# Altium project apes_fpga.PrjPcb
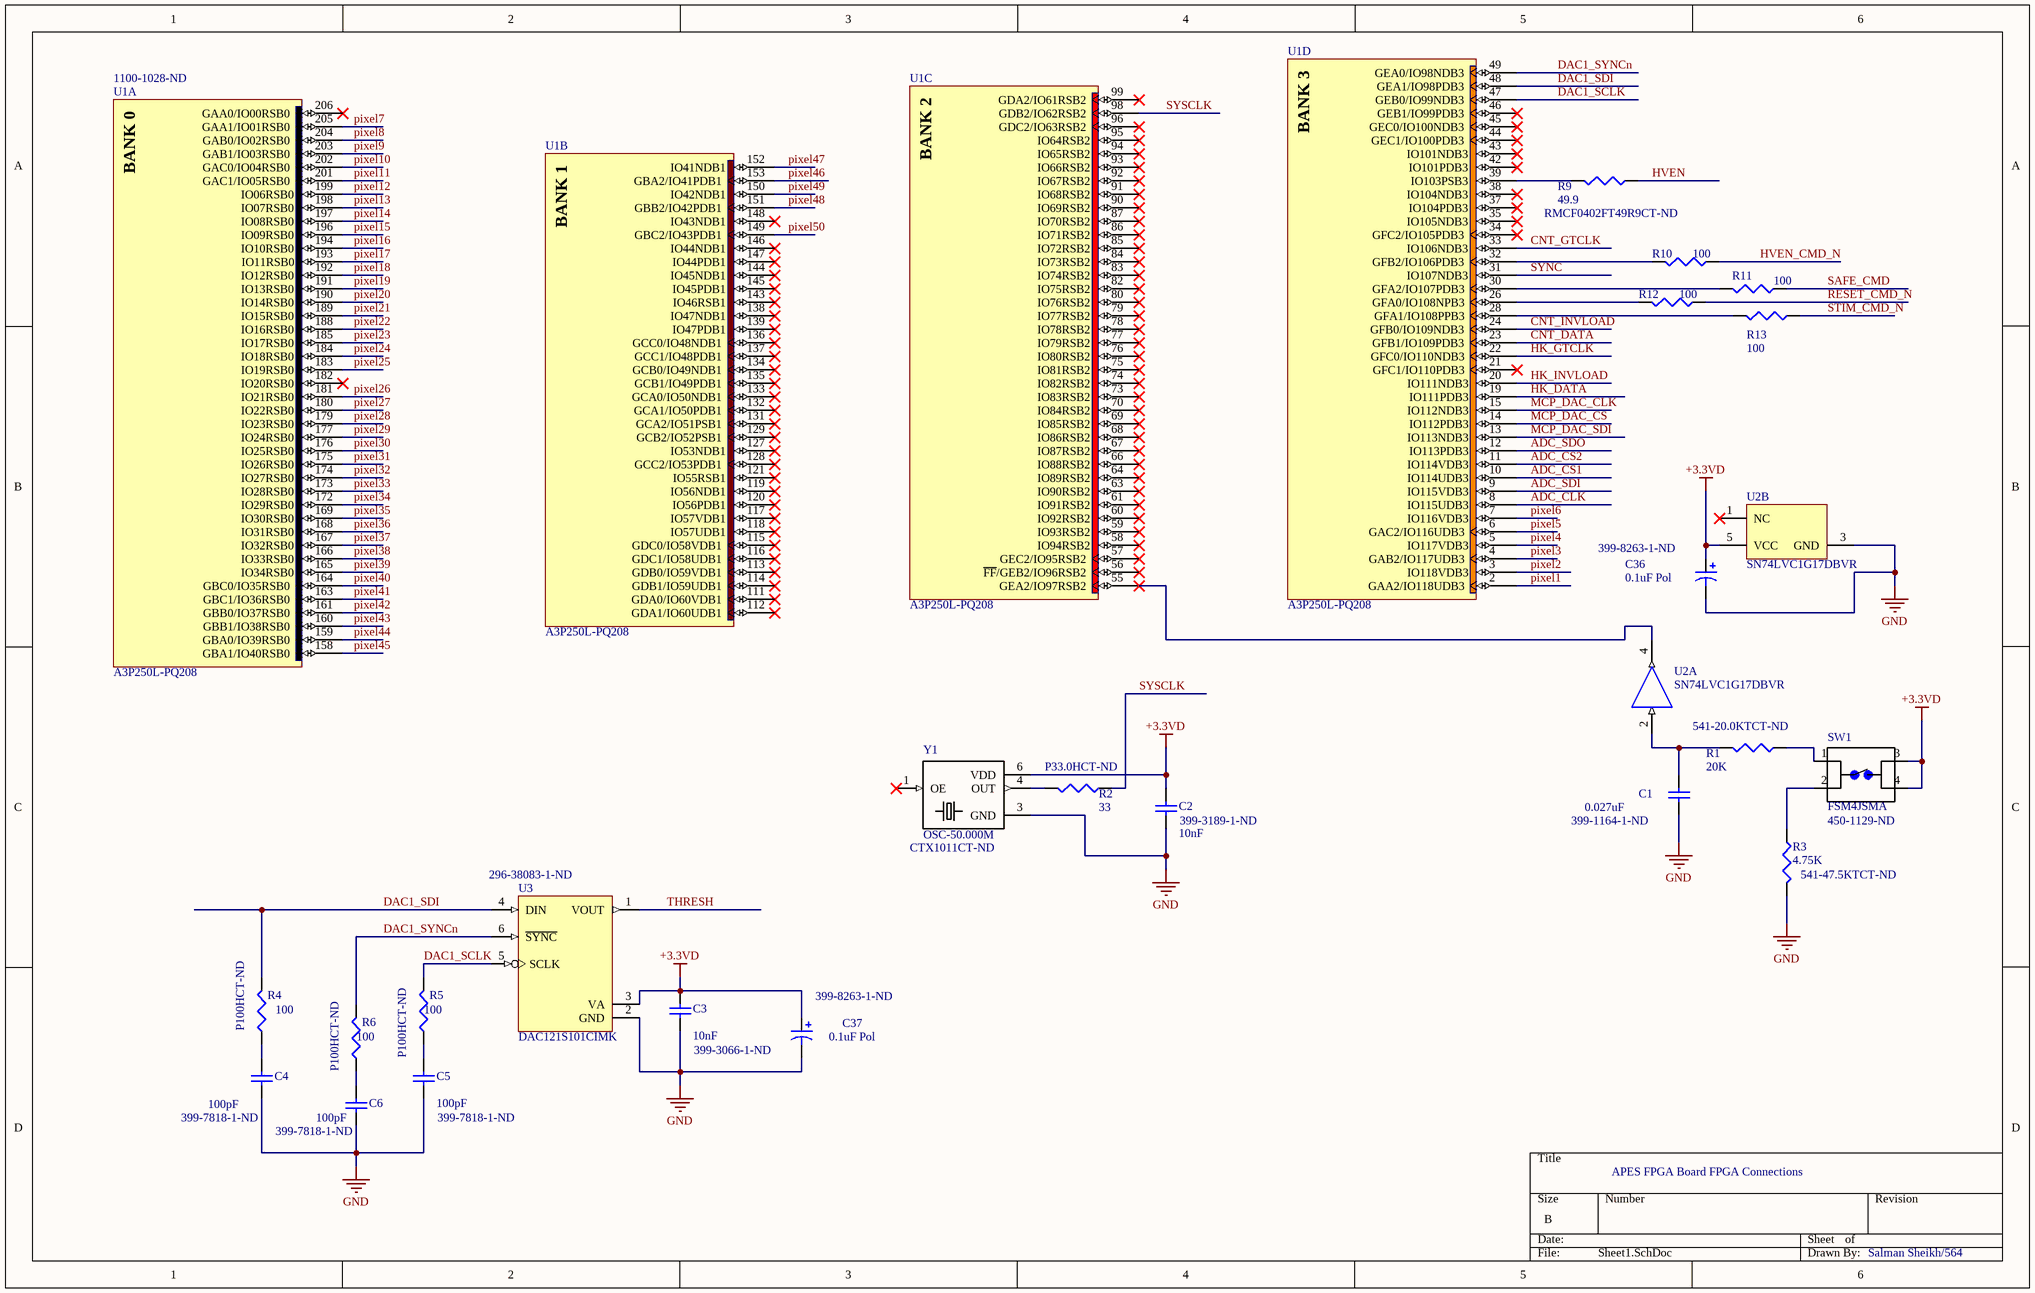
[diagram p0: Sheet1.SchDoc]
3 sheets, 66 parts. Net scope: global (net labels, ports and power ports of the same name join across sheets).
Board file: FPGA.PcbDoc
Sheets:
  Sheet1.SchDoc
  Sheet3.SchDoc
  Sheet2.SchDoc

## Sheet Sheet1.SchDoc
size B

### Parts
C1  value 0.027uF  Supplier Part Number 1: 399-1164-1-ND  [C0805]  (hidden comment: Cap Semi)
C2  value 10nF  Supplier Part Number 1: 399-3189-1-ND  [1608[0603]]  (hidden comment: Cap Semi)
C3  value 10nF  Supplier Part Number 1: 399-3066-1-ND  [0402]  (hidden comment: Cap Semi)
C4  value 100pF  Supplier Part Number 1: 399-7818-1-ND  [1608[0603]]  (hidden comment: Cap Semi)
C5  value 100pF  Supplier Part Number 1: 399-7818-1-ND  [1608[0603]]  (hidden comment: Cap Semi)
C6  value 100pF  Supplier Part Number 1: 399-7818-1-ND  [1608[0603]]  (hidden comment: Cap Semi)
C36  value 0.1uF Pol  Supplier Part Number 1: 399-8263-1-ND  [C0805]  (hidden comment: Cap Pol3)
C37  value 0.1uF Pol  Supplier Part Number 1: 399-8263-1-ND  [C0805]  (hidden comment: Cap Pol3)
R1  value 20K  Supplier Part Number 1: 541-20.0KTCT-ND  [J1-0603]  (hidden comment: Res3)
R2  value 33  Supplier Part Number 1: P33.0HCT-ND  [J1-0603]  (hidden comment: Res3)
R3  value 4.75K  Supplier Part Number 1: 541-47.5KTCT-ND  [J1-0603]  (hidden comment: Res3)
R4  value 100  Supplier Part Number 1: P100HCT-ND  [J1-0603]  (hidden comment: Res3)
R5  value 100  Supplier Part Number 1: P100HCT-ND  [J1-0603]  (hidden comment: Res3)
R6  value 100  Supplier Part Number 1: P100HCT-ND  [J1-0603]  (hidden comment: 0603)
R9  value 49.9  Supplier Part Number 1: RMCF0402FT49R9CT-ND  [J1-0603]  (hidden comment: Res3)
R10  value 100  [J1-0603]  (hidden comment: Res3)
R11  value 100  [J1-0603]  (hidden comment: Res3)
R12  value 100  [J1-0603]  (hidden comment: Res3)
R13  value 100  [J1-0603]  (hidden comment: Res3)
SW1  FSM4JSMA  Supplier Part Number 1: 450-1129-ND  [TE_FSM4JSMA]
U1  A3P250L-PQ208  Supplier Part Number 1: 1100-1028-ND  [PQ208_N]  (parts A,B,C,D of 9)
U2  SN74LVC1G17DBVR  (parts A,B of 2)
U3  DAC121S101CIMK  Supplier Part Number 1: 296-38083-1-ND  [MK06A_N]
Y1  OSC-50.000M  Supplier Part Number 1: CTX1011CT-ND  [XTAL_ECX-H22BN-10.000]

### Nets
+3.3VD: C2.2 C3.2 C36.1 C37.1 SW1.3 SW1.4 U2.5(VCC) U3.3(VA) Y1.6(VDD)
GND: C1.1 C2.1 C3.1 C4.1 C5.1 C6.1 C36.2 C37.2 R3.2 U2.3(GND) U3.2(GND) Y1.3(GND)
ADC_CLK: U1.8(IO115UDB3)
ADC_CS1: U1.10(IO114UDB3)
ADC_CS2: U1.11(IO114VDB3)
ADC_SDI: U1.9(IO115VDB3)
ADC_SDO: U1.12(IO113PDB3)
CNT_DATA: U1.23(GFB1/IO109PDB3)
CNT_GTCLK: U1.33(IO106NDB3)
CNT_INVLOAD: U1.24(GFB0/IO109NDB3)
DAC1_SCLK: R5.2 U1.47(GEB0/IO99NDB3) U3.5(SCLK)
DAC1_SDI: R4.2 U1.48(GEA1/IO98PDB3) U3.4(DIN)
DAC1_SYNCn: R6.2 U1.49(GEA0/IO98NDB3) U3.6(~{SYNC})
HK_DATA: U1.19(IO111PDB3)
HK_GTCLK: U1.22(GFC0/IO110NDB3)
HK_INVLOAD: U1.20(IO111NDB3)
HVEN: R9.1
HVEN_CMD_N: R10.1
MCP_DAC_CLK: U1.15(IO112NDB3)
MCP_DAC_CS: U1.14(IO112PDB3)
MCP_DAC_SDI: U1.13(IO113NDB3)
pixel1: U1.2(GAA2/IO118UDB3)
pixel2: U1.3(IO118VDB3)
pixel3: U1.4(GAB2/IO117UDB3)
pixel4: U1.5(IO117VDB3)
pixel5: U1.6(GAC2/IO116UDB3)
pixel6: U1.7(IO116VDB3)
pixel7: U1.205(GAA1/IO01RSB0)
pixel8: U1.204(GAB0/IO02RSB0)
pixel9: U1.203(GAB1/IO03RSB0)
pixel10: U1.202(GAC0/IO04RSB0)
pixel11: U1.201(GAC1/IO05RSB0)
pixel12: U1.199(IO06RSB0)
pixel13: U1.198(IO07RSB0)
pixel14: U1.197(IO08RSB0)
pixel15: U1.196(IO09RSB0)
pixel16: U1.194(IO10RSB0)
pixel17: U1.193(IO11RSB0)
pixel18: U1.192(IO12RSB0)
pixel19: U1.191(IO13RSB0)
pixel20: U1.190(IO14RSB0)
pixel21: U1.189(IO15RSB0)
pixel22: U1.188(IO16RSB0)
pixel23: U1.185(IO17RSB0)
pixel24: U1.184(IO18RSB0)
pixel25: U1.183(IO19RSB0)
pixel26: U1.181(IO21RSB0)
pixel27: U1.180(IO22RSB0)
pixel28: U1.179(IO23RSB0)
pixel29: U1.177(IO24RSB0)
pixel30: U1.176(IO25RSB0)
pixel31: U1.175(IO26RSB0)
pixel32: U1.174(IO27RSB0)
pixel33: U1.173(IO28RSB0)
pixel34: U1.172(IO29RSB0)
pixel35: U1.169(IO30RSB0)
pixel36: U1.168(IO31RSB0)
pixel37: U1.167(IO32RSB0)
pixel38: U1.166(IO33RSB0)
pixel39: U1.165(IO34RSB0)
pixel40: U1.164(GBC0/IO35RSB0)
pixel41: U1.163(GBC1/IO36RSB0)
pixel42: U1.161(GBB0/IO37RSB0)
pixel43: U1.160(GBB1/IO38RSB0)
pixel44: U1.159(GBA0/IO39RSB0)
pixel45: U1.158(GBA1/IO40RSB0)
pixel46: U1.153(GBA2/IO41PDB1)
pixel47: U1.152(IO41NDB1)
pixel48: U1.151(GBB2/IO42PDB1)
pixel49: U1.150(IO42NDB1)
pixel50: U1.149(GBC2/IO43PDB1)
RESET_CMD_N: R12.1
SAFE_CMD: R11.1
STIM_CMD_N: R13.1
SYNC: U1.31(IO107NDB3)
SYSCLK: R2.1 U1.98(GDB2/IO62RSB2)
THRESH: U3.1(VOUT)
NetC1_2: C1.2 R1.2 U2.2(A)
NetC4_2: C4.2 R4.1
NetC5_2: C5.2 R5.1
NetC6_2: C6.2 R6.1
NetR1_1: R1.1 SW1.1
NetR2_2: R2.2 Y1.4(OUT)
NetR3_1: R3.1 SW1.2
NetR9_2: R9.2 U1.39(IO103PSB3)
NetR10_2: R10.2 U1.32(GFB2/IO106PDB3)
NetR11_2: R11.2 U1.30(GFA2/IO107PDB3)
NetR12_2: R12.2 U1.26(GFA0/IO108NPB3)
NetR13_2: R13.2 U1.28(GFA1/IO108PPB3)
NetU1_55: U1.55(GEA2/IO97RSB2) U2.4(Y)

Not connected (* = marked no-connect by the designer): U1 21(GFC1/IO110PDB3)* 34(GFC2/IO105PDB3)* 35(IO105NDB3)* 37(IO104PDB3)* 38(IO104NDB3)* 42(IO101PDB3)* 43(IO101NDB3)* 44(GEC1/IO100PDB3)* 45(GEC0/IO100NDB3)* 46(GEB1/IO99PDB3)* 56(~{FF}/GEB2/IO96RSB2)* 57(GEC2/IO95RSB2)* 58(IO94RSB2)* 59(IO93RSB2)* 60(IO92RSB2)* 61(IO91RSB2)* 63(IO90RSB2)* 64(IO89RSB2)* 66(IO88RSB2)* 67(IO87RSB2)* 68(IO86RSB2)* 69(IO85RSB2)* 70(IO84RSB2)* 73(IO83RSB2)* 74(IO82RSB2)* 75(IO81RSB2)* 76(IO80RSB2)* 77(IO79RSB2)* 78(IO78RSB2)* 79(IO77RSB2)* 80(IO76RSB2)* 82(IO75RSB2)* 83(IO74RSB2)* 84(IO73RSB2)* 85(IO72RSB2)* 86(IO71RSB2)* 87(IO70RSB2)* 90(IO69RSB2)* 91(IO68RSB2)* 92(IO67RSB2)* 93(IO66RSB2)* 94(IO65RSB2)* 95(IO64RSB2)* 96(GDC2/IO63RSB2)* 99(GDA2/IO61RSB2)* 111(GDA0/IO60VDB1)* 112(GDA1/IO60UDB1)* 113(GDB0/IO59VDB1)* 114(GDB1/IO59UDB1)* 115(GDC0/IO58VDB1)* 116(GDC1/IO58UDB1)* 117(IO57VDB1)* 118(IO57UDB1)* 119(IO56NDB1)* 120(IO56PDB1)* 121(IO55RSB1)* 127(IO53NDB1)* 128(GCC2/IO53PDB1)* 129(GCB2/IO52PSB1)* 131(GCA2/IO51PSB1)* 132(GCA1/IO50PDB1)* 133(GCA0/IO50NDB1)* 134(GCB0/IO49NDB1)* 135(GCB1/IO49PDB1)* 136(GCC0/IO48NDB1)* 137(GCC1/IO48PDB1)* 138(IO47NDB1)* 139(IO47PDB1)* 143(IO46RSB1)* 144(IO45NDB1)* 145(IO45PDB1)* 146(IO44NDB1)* 147(IO44PDB1)* 148(IO43NDB1)* 182(IO20RSB0)* 206(GAA0/IO00RSB0)*; U2 1(NC)*; Y1 1(OE)*

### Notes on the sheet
- APES FPGA Board FPGA Connections
- Salman Sheikh/564

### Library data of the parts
C1 = Cap Semi: 0.027uF
C2 C3 = Cap Semi: 10nF
C4-C6 = Cap Semi: 100pF
C36 C37 = Cap Pol3: 0.1uF pol
R1 = Res3: 20K
R2 = Res3: 33ohm
R3 = Res3: 4.75K
R4-R6 R10-R13 = Res3: 100ohm
R9 = Res3: 49.9
SW1 = FSM4JSMA: PB SW; MP: FSM-4J-SMA; MF: TE Connectivity
U1 = A3P250L-PQ208: ProASIC3L Low-Power Flash Family FPGA, 151 User IOs, 250K System Gates, 36 Kbits RAM, 1 Kbit FlashROM, 1PLL, 208-Pin PQFP, Commercial Grade
U2 = SN74LVC1G17DBVR: Single Schmitt-Trigger Buffer, DBV0005A, LARGE T&R; Manufacturer: Texas Instruments; VCC(Min)(V): 1.65; VCC(Max)(V): 5.5; Output Type: CMOS; ICC @ Nom Voltage(Max)(mA): 0.01; Input Type: CMOS/TTL; Bits(#): 1; F @ Nom Voltage(Max)(Mhz): 150; Rating: Catalog; Technology Family: LVC; Voltage(Nom)(V): 1.8,2.5,3.3,5; Schmitt Trigger: Yes; Output Drive (IOL/IOH)(Max)(mA): 32/-32; tpd @ Nom Voltage(Max)(ns): 11,6.5,5.5,5; Logic: True; Sub-Family: Non-Inverting Buffer/Driver; 3-State Output: No
U3 = DAC121S101CIMK: 12-Bit Micro Power Digital-to-Analog Converter with Rail-to-Rail Output, 6-pin Tiny SOT23; Manufacturer: National Semiconductor; PackageTopMarking: X61C*XTT; PowerWise: Y; CompType: D/A Converter
Y1 = ECX-H22CM-50.000: OSC XO 50.0000MHZ HCMOS SMD; MF: ECS International

## Sheet Sheet3.SchDoc
size B
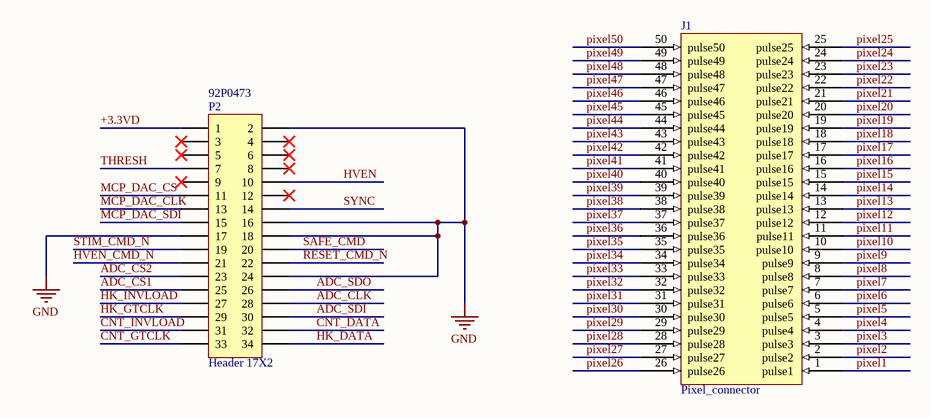
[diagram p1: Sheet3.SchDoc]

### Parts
J1  Pixel_connector  [pixel50_conn]
P2  Header 17X2  Supplier Part Number 1: 92P0473  [HDR2X17]

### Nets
+3.3VD: P2.1
GND: P2.2 P2.16 P2.17 P2.18 P2.24
ADC_CLK: P2.28
ADC_CS1: P2.25
ADC_CS2: P2.23
ADC_SDI: P2.30
ADC_SDO: P2.26
CNT_DATA: P2.32
CNT_GTCLK: P2.33
CNT_INVLOAD: P2.31
HK_DATA: P2.34
HK_GTCLK: P2.29
HK_INVLOAD: P2.27
HVEN: P2.10
HVEN_CMD_N: P2.21
MCP_DAC_CLK: P2.13
MCP_DAC_CS: P2.11
MCP_DAC_SDI: P2.15
pixel1: J1.1(pulse1)
pixel2: J1.2(pulse2)
pixel3: J1.3(pulse3)
pixel4: J1.4(pulse4)
pixel5: J1.5(pulse5)
pixel6: J1.6(pulse6)
pixel7: J1.7(pulse7)
pixel8: J1.8(pulse8)
pixel9: J1.9(pulse9)
pixel10: J1.10(pulse10)
pixel11: J1.11(pulse11)
pixel12: J1.12(pulse12)
pixel13: J1.13(pulse13)
pixel14: J1.14(pulse14)
pixel15: J1.15(pulse15)
pixel16: J1.16(pulse16)
pixel17: J1.17(pulse17)
pixel18: J1.18(pulse18)
pixel19: J1.19(pulse19)
pixel20: J1.20(pulse20)
pixel21: J1.21(pulse21)
pixel22: J1.22(pulse22)
pixel23: J1.23(pulse23)
pixel24: J1.24(pulse24)
pixel25: J1.25(pulse25)
pixel26: J1.26(pulse26)
pixel27: J1.27(pulse27)
pixel28: J1.28(pulse28)
pixel29: J1.29(pulse29)
pixel30: J1.30(pulse30)
pixel31: J1.31(pulse31)
pixel32: J1.32(pulse32)
pixel33: J1.33(pulse33)
pixel34: J1.34(pulse34)
pixel35: J1.35(pulse35)
pixel36: J1.36(pulse36)
pixel37: J1.37(pulse37)
pixel38: J1.38(pulse38)
pixel39: J1.39(pulse39)
pixel40: J1.40(pulse40)
pixel41: J1.41(pulse41)
pixel42: J1.42(pulse42)
pixel43: J1.43(pulse43)
pixel44: J1.44(pulse44)
pixel45: J1.45(pulse45)
pixel46: J1.46(pulse46)
pixel47: J1.47(pulse47)
pixel48: J1.48(pulse48)
pixel49: J1.49(pulse49)
pixel50: J1.50(pulse50)
RESET_CMD_N: P2.22
SAFE_CMD: P2.20
STIM_CMD_N: P2.19
SYNC: P2.14
THRESH: P2.7

Not connected (* = marked no-connect by the designer): P2 3* 4* 5* 6* 8* 9* 12*

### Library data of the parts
J1 = Pixel_connector: CustomPins
P2 = Header 17X2: Header, 17-Pin, Dual row

## Sheet Sheet2.SchDoc
size B
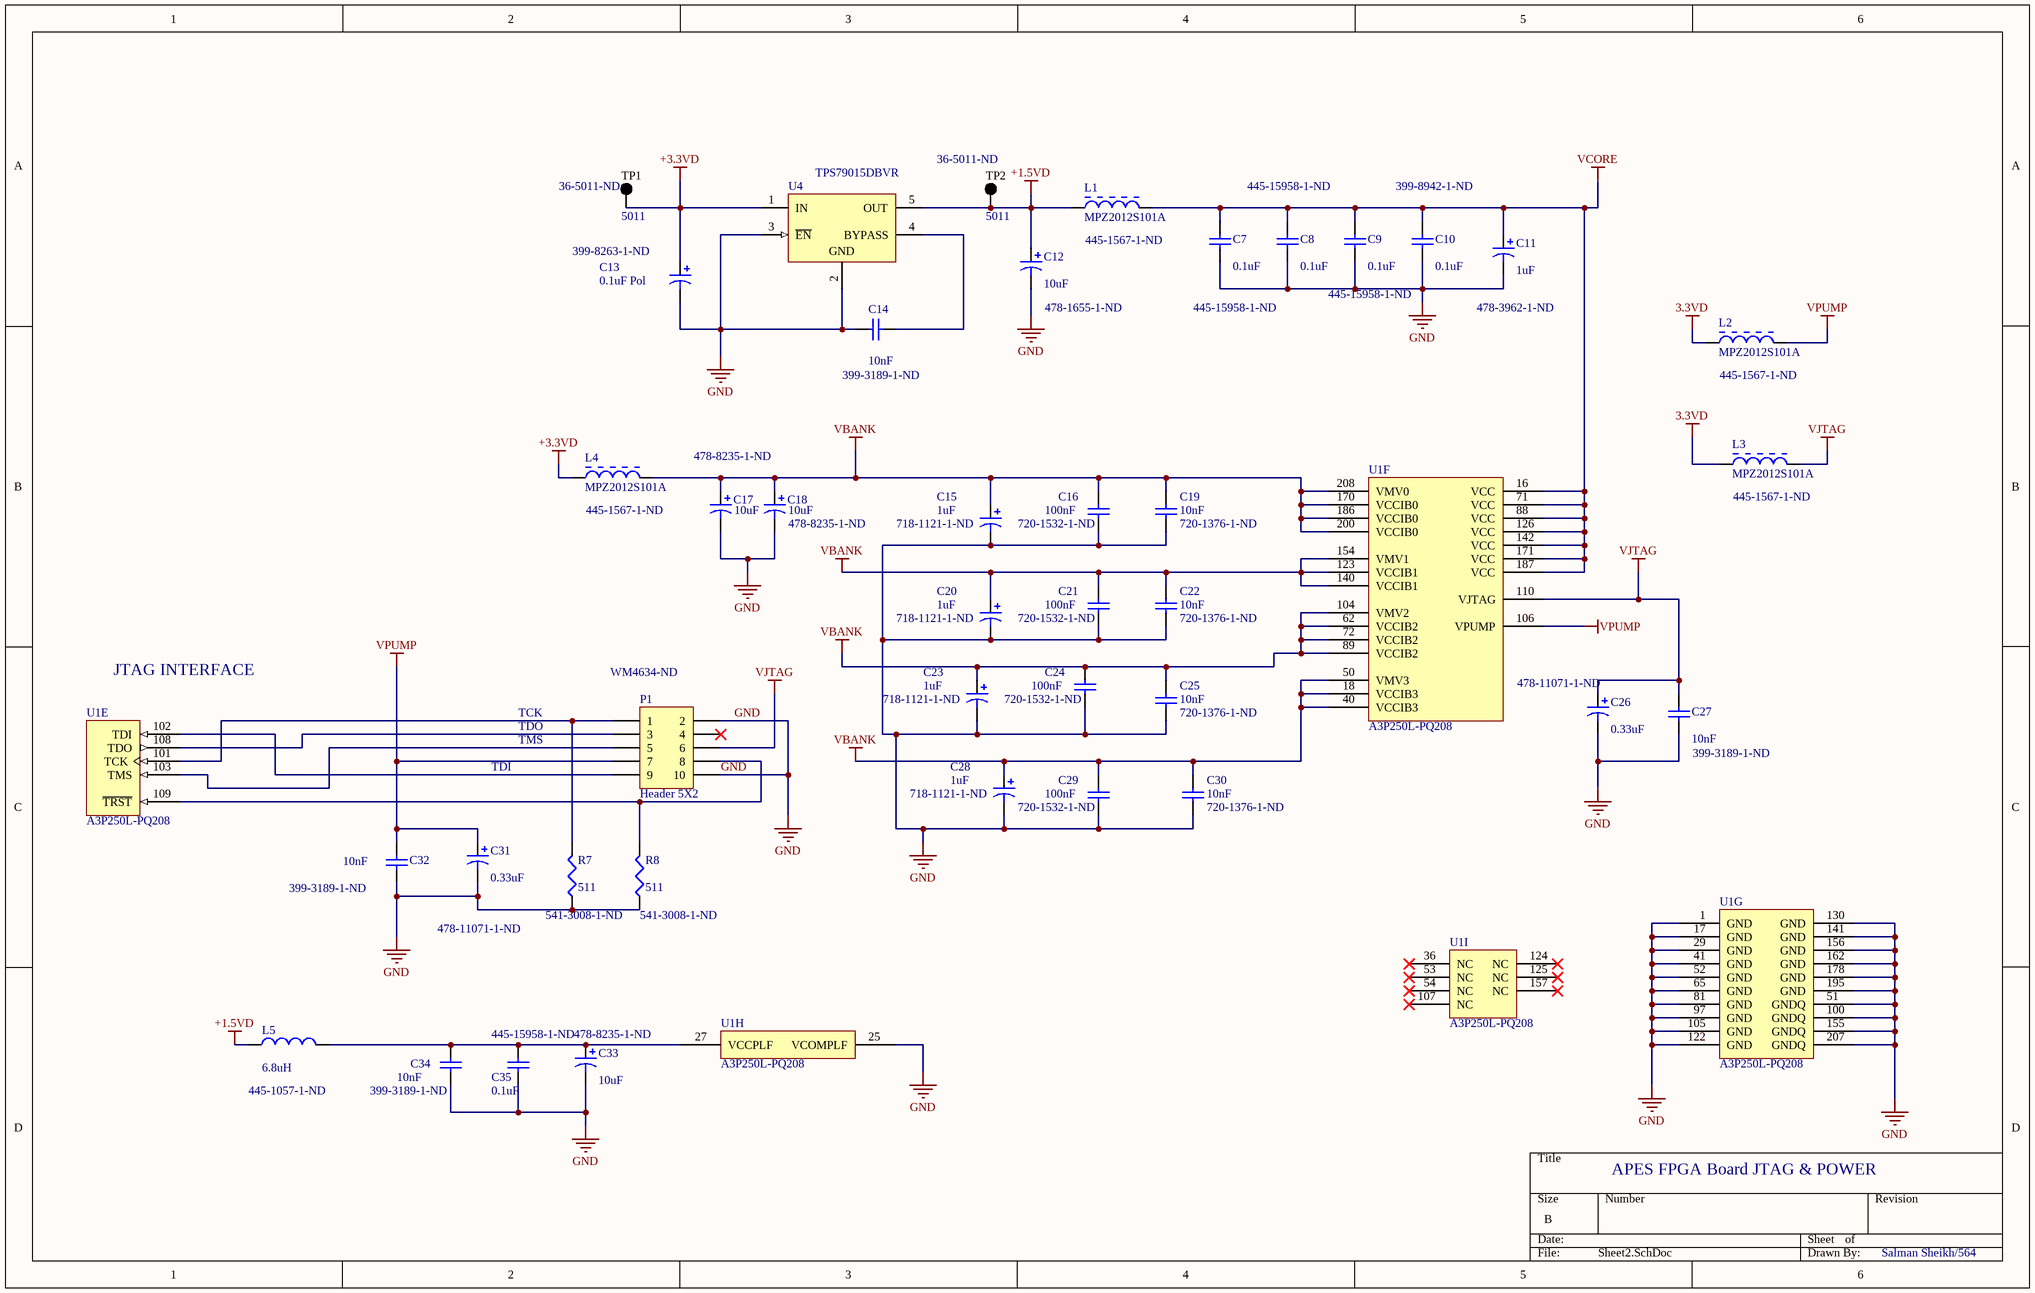
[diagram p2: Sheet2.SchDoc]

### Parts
C7  value 0.1uF  Supplier Part Number 1: 445-15958-1-ND  [0402-A]  (hidden comment: Cap Semi)
C8  value 0.1uF  Supplier Part Number 1: 445-15958-1-ND  [0402-A]  (hidden comment: Cap Semi)
C9  value 0.1uF  Supplier Part Number 1: 445-15958-1-ND  [0402-A]  (hidden comment: Cap Semi)
C10  value 0.1uF  Supplier Part Number 1: 399-8942-1-ND  [0402-A]  (hidden comment: Cap Semi)
C11  value 1uF  Supplier Part Number 1: 478-3962-1-ND  [C0805]  (hidden comment: Cap Pol3)
C12  value 10uF  Supplier Part Number 1: 478-1655-1-ND  [C0805]  (hidden comment: Cap Pol3)
C13  value 0.1uF Pol  Supplier Part Number 1: 399-8263-1-ND  [C0805]  (hidden comment: Cap Pol3)
C14  value 10nF  Supplier Part Number 1: 399-3189-1-ND  [1608[0603]]  (hidden comment: Cap Semi)
C15  value 1uF  Supplier Part Number 1: 718-1121-1-ND  [C0805]  (hidden comment: Cap Pol3)
C16  value 100nF  Supplier Part Number 1: 720-1532-1-ND  [0402-A]  (hidden comment: Cap Semi)
C17  value 10uF  Supplier Part Number 1: 478-8235-1-ND  [C1206]  (hidden comment: Cap Pol3)
C18  value 10uF  Supplier Part Number 1: 478-8235-1-ND  [C1206]  (hidden comment: Cap Pol3)
C19  value 10nF  Supplier Part Number 1: 720-1376-1-ND  [0402-A]  (hidden comment: Cap Semi)
C20  value 1uF  Supplier Part Number 1: 718-1121-1-ND  [C0805]  (hidden comment: Cap Pol3)
C21  value 100nF  Supplier Part Number 1: 720-1532-1-ND  [0402-A]  (hidden comment: Cap Semi)
C22  value 10nF  Supplier Part Number 1: 720-1376-1-ND  [0402-A]  (hidden comment: Cap Semi)
C23  value 1uF  Supplier Part Number 1: 718-1121-1-ND  [C0805]  (hidden comment: Cap Pol3)
C24  value 100nF  Supplier Part Number 1: 720-1532-1-ND  [0402-A]  (hidden comment: Cap Semi)
C25  value 10nF  Supplier Part Number 1: 720-1376-1-ND  [0402-A]  (hidden comment: Cap Semi)
C26  value 0.33uF  Supplier Part Number 1: 478-11071-1-ND  [C0805]  (hidden comment: Cap Pol3)
C27  value 10nF  Supplier Part Number 1: 399-3189-1-ND  [1608[0603]]  (hidden comment: Cap Semi)
C28  value 1uF  Supplier Part Number 1: 718-1121-1-ND  [C0805]  (hidden comment: Cap Pol3)
C29  value 100nF  Supplier Part Number 1: 720-1532-1-ND  [0402-A]  (hidden comment: Cap Semi)
C30  value 10nF  Supplier Part Number 1: 720-1376-1-ND  [0402-A]  (hidden comment: Cap Semi)
C31  value 0.33uF  Supplier Part Number 1: 478-11071-1-ND  [C0805]  (hidden comment: Cap Pol3)
C32  value 10nF  Supplier Part Number 1: 399-3189-1-ND  [1608[0603]]  (hidden comment: Cap Semi)
C33  value 10uF  Supplier Part Number 1: 478-8235-1-ND  [C1206]  (hidden comment: Cap Pol3)
C34  value 10nF  Supplier Part Number 1: 399-3189-1-ND  [1608[0603]]  (hidden comment: Cap Semi)
C35  value 0.1uF  Supplier Part Number 1: 445-15958-1-ND  [1608[0603]]  (hidden comment: Cap Semi)
L1  MPZ2012S101A  Supplier Part Number 1: 445-1567-1-ND  [LIRD-LI0805H151R-10-2_V]
L2  MPZ2012S101A  Supplier Part Number 1: 445-1567-1-ND  [LIRD-LI0805H151R-10-2_V]
L3  MPZ2012S101A  Supplier Part Number 1: 445-1567-1-ND  [LIRD-LI0805H151R-10-2_V]
L4  MPZ2012S101A  Supplier Part Number 1: 445-1567-1-ND  [LIRD-LI0805H151R-10-2_V]
L5  value 6.8uH  Supplier Part Number 1: 445-1057-1-ND  [C0805]
P1  Header 5X2  Supplier Part Number 1: WM4634-ND  [HDR2X5]
R7  value 511  Supplier Part Number 1: 541-3008-1-ND  [J1-0603]  (hidden comment: Res3)
R8  value 511  Supplier Part Number 1: 541-3008-1-ND  [J1-0603]  (hidden comment: Res3)
TP1  5011  Supplier Part Number 1: 36-5011-ND  [KSTN-5011_V]
TP2  5011  Supplier Part Number 1: 36-5011-ND  [KSTN-5011_V]
U1  A3P250L-PQ208  [PQ208_N]  (parts E,F,G,H,I of 9)
U4  TPS79015DBVR  [SOT23-5]

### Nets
3.3VD: L2.1 L3.1
+1.5VD: C12.1 L1.1 L5.1 TP2.1 U4.5(OUT)
+3.3VD: C13.1 L4.1 TP1.1 U4.1(IN)
GND: C7.1 C8.1 C9.1 C10.1 C11.2 C12.2 C13.2 C14.1 C15.2 C16.1 C17.2 C18.2 C19.1 C20.2 C21.1 C22.1 C23.2 C24.1 C25.1 C26.2 C27.1 C28.2 C29.1 C30.1 C31.2 C32.1 C33.2 C34.1 C35.1 P1.2 P1.10 R7.1 R8.1 U1.1(GND) U1.17(GND) U1.25(VCOMPLF) U1.29(GND) U1.41(GND) U1.51(GNDQ) U1.52(GND) U1.65(GND) U1.81(GND) U1.97(GND) U1.100(GNDQ) U1.105(GND) U1.122(GND) U1.130(GND) U1.141(GND) U1.155(GNDQ) U1.156(GND) U1.162(GND) U1.178(GND) U1.195(GND) U1.207(GNDQ) U4.2(GND) U4.3(~{EN})
VBANK: C15.1 C16.2 C17.1 C18.1 C19.2 C20.1 C21.2 C22.2 C23.1 C24.2 C25.2 C28.1 C29.2 C30.2 L4.2 U1.18(VCCIB3) U1.40(VCCIB3) U1.50(VMV3) U1.62(VCCIB2) U1.72(VCCIB2) U1.89(VCCIB2) U1.104(VMV2) U1.123(VCCIB1) U1.140(VCCIB1) U1.154(VMV1) U1.170(VCCIB0) U1.186(VCCIB0) U1.200(VCCIB0) U1.208(VMV0)
VCORE: C7.2 C8.2 C9.2 C10.2 C11.1 L1.2 U1.16(VCC) U1.71(VCC) U1.88(VCC) U1.126(VCC) U1.142(VCC) U1.171(VCC) U1.187(VCC)
VJTAG: C26.1 C27.2 L3.2 P1.6 U1.110(VJTAG)
VPUMP: C31.1 C32.2 L2.2 P1.7 U1.106(VPUMP)
NetC14_2: C14.2 U4.4(BYPASS)
NetC33_1: C33.1 C34.2 C35.2 L5.2 U1.27(VCCPLF)
NetP1_1: P1.1 R7.2 U1.101(TCK)
NetP1_3: P1.3 U1.108(TDO)
NetP1_5: P1.5 U1.103(TMS)
NetP1_8: P1.8 R8.2 U1.109(~{TRST})
NetP1_9: P1.9 U1.102(TDI)

Not connected (* = marked no-connect by the designer): P1 4*; U1 36(NC)* 53(NC)* 54(NC)* 107(NC)* 124(NC)* 125(NC)* 157(NC)*

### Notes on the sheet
- JTAG INTERFACE
- TDI
- TCK
- TDO
- TMS
- APES FPGA Board JTAG & POWER
- Salman Sheikh/564

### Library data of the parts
C7-C10 C35 = Cap Semi: 0.1uF
C11 = Cap Pol3: 1uF Pol
C12 C17 C18 = Cap Pol3: 10uF Pol
C13 = Cap Pol3: 0.1uF pol
C14 C19 C22 C25 C27 C30 C32 C34 = Cap Semi: 10nF
C15 C20 C23 C28 = Cap Pol3: 1uF
C16 C21 C24 C29 = Cap Semi: 100nF
C26 C31 = Cap Pol3: 0.33uF Pol
C33 = Cap Pol3: 10 uF
L1-L4 = CMP-2000-06404-1: FB, 100ohm; Manufacturer: Laird; DC Resistance (DCR) (Max): 10mOhm; Current Rating (Max): 5A; Kits: 240-2227-ND-KITEMIFERRITEBEADCHIPSMD; Filter Type: Power,SignalLine; Impedance @ Frequency: 80Ohm@100MHz; Online Catalog: HISeries; Other Names: 240-2395-1; Catalog Drawings: (HI,HZ,LI,MI)0805Series_1.10mmMax.Height; Package Version: Rev. D, 08/2013; Number of Lines: 1
L5 = Inductor: Code_IEC: 1005
P1 = Header 5X2: Header, 5-Pin, Dual row
R7 R8 = Res3: 511ohm
TP1 TP2 = CMP-1672-00003-4: Test Point, Black, Through Hole, RoHS, Bulk; Manufacturer: Keystone
U1 = A3P250L-PQ208: as U1 on sheet Sheet1
U4 = TPS79015DBVR: Single Output Low Noise LDO, 50 mA, Fixed 1.5 V Output, 2.7 to 10 V Input, with Low IQ, 5-pin SOT-23 (DBV), -40 to 125 degC, Green (RoHS & no Sb/Br); Manufacturer: Texas Instruments; Fixed Output Options(V): 1.5; Iout(Max)(A): 0.05; Iq(Typ)(mA): 0.02; Rating: Catalog; SubFamily: Single Channel LDO; Vdo(Typ)(mV): 57; Vin(Max)(V): 10; Vin(Min)(V): 2.7

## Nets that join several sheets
+3.3VD: Sheet1 (9 pins), Sheet3 (P2.1), Sheet2 (C13.1 L4.1 TP1.1 U4.1)
GND: Sheet1 (12 pins), Sheet3 (5 pins), Sheet2 (56 pins)
ADC_CLK: Sheet1 (U1.8), Sheet3 (P2.28)
ADC_CS1: Sheet1 (U1.10), Sheet3 (P2.25)
ADC_CS2: Sheet1 (U1.11), Sheet3 (P2.23)
ADC_SDI: Sheet1 (U1.9), Sheet3 (P2.30)
ADC_SDO: Sheet1 (U1.12), Sheet3 (P2.26)
CNT_DATA: Sheet1 (U1.23), Sheet3 (P2.32)
CNT_GTCLK: Sheet1 (U1.33), Sheet3 (P2.33)
CNT_INVLOAD: Sheet1 (U1.24), Sheet3 (P2.31)
HK_DATA: Sheet1 (U1.19), Sheet3 (P2.34)
HK_GTCLK: Sheet1 (U1.22), Sheet3 (P2.29)
HK_INVLOAD: Sheet1 (U1.20), Sheet3 (P2.27)
HVEN: Sheet1 (R9.1), Sheet3 (P2.10)
HVEN_CMD_N: Sheet1 (R10.1), Sheet3 (P2.21)
MCP_DAC_CLK: Sheet1 (U1.15), Sheet3 (P2.13)
MCP_DAC_CS: Sheet1 (U1.14), Sheet3 (P2.11)
MCP_DAC_SDI: Sheet1 (U1.13), Sheet3 (P2.15)
pixel1: Sheet1 (U1.2), Sheet3 (J1.1)
pixel2: Sheet1 (U1.3), Sheet3 (J1.2)
pixel3: Sheet1 (U1.4), Sheet3 (J1.3)
pixel4: Sheet1 (U1.5), Sheet3 (J1.4)
pixel5: Sheet1 (U1.6), Sheet3 (J1.5)
pixel6: Sheet1 (U1.7), Sheet3 (J1.6)
pixel7: Sheet1 (U1.205), Sheet3 (J1.7)
pixel8: Sheet1 (U1.204), Sheet3 (J1.8)
pixel9: Sheet1 (U1.203), Sheet3 (J1.9)
pixel10: Sheet1 (U1.202), Sheet3 (J1.10)
pixel11: Sheet1 (U1.201), Sheet3 (J1.11)
pixel12: Sheet1 (U1.199), Sheet3 (J1.12)
pixel13: Sheet1 (U1.198), Sheet3 (J1.13)
pixel14: Sheet1 (U1.197), Sheet3 (J1.14)
pixel15: Sheet1 (U1.196), Sheet3 (J1.15)
pixel16: Sheet1 (U1.194), Sheet3 (J1.16)
pixel17: Sheet1 (U1.193), Sheet3 (J1.17)
pixel18: Sheet1 (U1.192), Sheet3 (J1.18)
pixel19: Sheet1 (U1.191), Sheet3 (J1.19)
pixel20: Sheet1 (U1.190), Sheet3 (J1.20)
pixel21: Sheet1 (U1.189), Sheet3 (J1.21)
pixel22: Sheet1 (U1.188), Sheet3 (J1.22)
pixel23: Sheet1 (U1.185), Sheet3 (J1.23)
pixel24: Sheet1 (U1.184), Sheet3 (J1.24)
pixel25: Sheet1 (U1.183), Sheet3 (J1.25)
pixel26: Sheet1 (U1.181), Sheet3 (J1.26)
pixel27: Sheet1 (U1.180), Sheet3 (J1.27)
pixel28: Sheet1 (U1.179), Sheet3 (J1.28)
pixel29: Sheet1 (U1.177), Sheet3 (J1.29)
pixel30: Sheet1 (U1.176), Sheet3 (J1.30)
pixel31: Sheet1 (U1.175), Sheet3 (J1.31)
pixel32: Sheet1 (U1.174), Sheet3 (J1.32)
pixel33: Sheet1 (U1.173), Sheet3 (J1.33)
pixel34: Sheet1 (U1.172), Sheet3 (J1.34)
pixel35: Sheet1 (U1.169), Sheet3 (J1.35)
pixel36: Sheet1 (U1.168), Sheet3 (J1.36)
pixel37: Sheet1 (U1.167), Sheet3 (J1.37)
pixel38: Sheet1 (U1.166), Sheet3 (J1.38)
pixel39: Sheet1 (U1.165), Sheet3 (J1.39)
pixel40: Sheet1 (U1.164), Sheet3 (J1.40)
pixel41: Sheet1 (U1.163), Sheet3 (J1.41)
pixel42: Sheet1 (U1.161), Sheet3 (J1.42)
pixel43: Sheet1 (U1.160), Sheet3 (J1.43)
pixel44: Sheet1 (U1.159), Sheet3 (J1.44)
pixel45: Sheet1 (U1.158), Sheet3 (J1.45)
pixel46: Sheet1 (U1.153), Sheet3 (J1.46)
pixel47: Sheet1 (U1.152), Sheet3 (J1.47)
pixel48: Sheet1 (U1.151), Sheet3 (J1.48)
pixel49: Sheet1 (U1.150), Sheet3 (J1.49)
pixel50: Sheet1 (U1.149), Sheet3 (J1.50)
RESET_CMD_N: Sheet1 (R12.1), Sheet3 (P2.22)
SAFE_CMD: Sheet1 (R11.1), Sheet3 (P2.20)
STIM_CMD_N: Sheet1 (R13.1), Sheet3 (P2.19)
SYNC: Sheet1 (U1.31), Sheet3 (P2.14)
THRESH: Sheet1 (U3.1), Sheet3 (P2.7)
